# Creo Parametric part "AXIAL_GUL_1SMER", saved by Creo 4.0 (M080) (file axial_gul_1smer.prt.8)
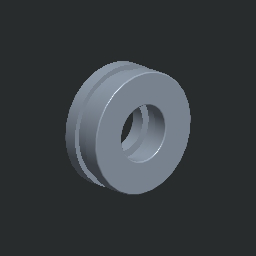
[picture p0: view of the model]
Units: Custom; MM, KILOGRAM, SECS

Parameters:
  MFG_WP_MATERIAL = "OCEL"
  NAZOV = "AXIAL_GUL_1SMER"
  PTC_MATERIAL_NAME = "OCEL_N"

Other parameters: HMOTNOST, HUSTOTA, D8, D9, D10, D11

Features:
  1. round

Named dimensions: velke_D1, velke_D

Layers: 1, 2, 3, 4, 5, 6, 7, 8, 9, 10, 11, 12, 13, 14, 15, 16, 17, 18, 19, 20, 21, 22, 23, 24, 25, 26, 27, 28, 29, 30, 31, 32

Family table entries: GENERIC, LOZISKO_51100A, AXIAL_GUL_1SMER, value(d_val), 2/8, 2/8, 2/&, 2/", value(i_val), LOZISKO_51200, AXIAL_GUL_1SMER, !/$, 2/:, 2/:, 2/(, 2/&, LOZISKO_51101A, AXIAL_GUL_1SMER, !/(, 2/:, 2/:, 2/*, 2/", value(s_val), _LOZISKO_51101A, (PRO_MP_CSYS, LOZISKO_51201, AXIAL_GUL_1SMER,  2/(, 2/<, 2/<, 2/,, 2/&, LOZISKO_51102A, AXIAL_GUL_1SMER, !/., 2/<, 2/<, 2/0, 2/"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

Surfaces: 12 cylinder, 8 torus, 6 plane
